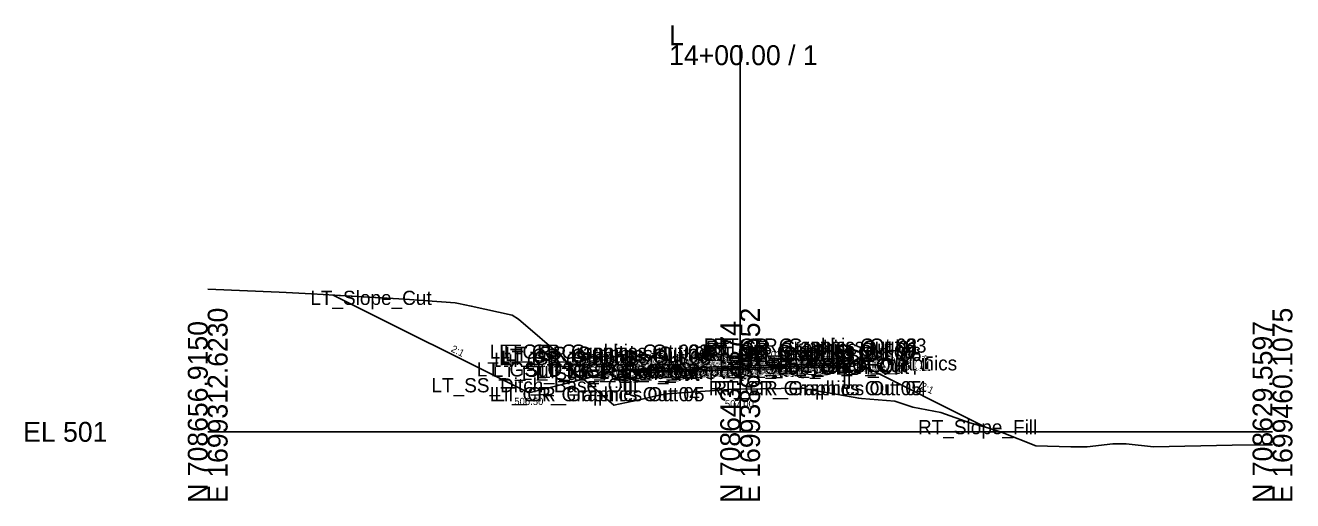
# Model space of a CAD drawing. Extents: x -63 to 1153, y -24 to 9522.
# Drawn here: x -25.7 to 152.8, y 4490.3 to 4557.3 of the extents above; entities that cross this region are included whole.
import ezdxf

# ---------------------------------------------------------------- set-up
doc = ezdxf.new("R2010")
doc.units = 0
for name, color, linetype in [('Default', 7, 'Continuous'), ('Exist Cross Section Cell', 7, 'Continuous'), ('Exist XS Center Line Elevation Label', 7, 'Continuous'), ('Exist XS Ground Line', 7, 'Continuous'), ('Prop CMT DNC', 7, 'Continuous'), ('Prop CMT Guardrail Graphics', 7, 'Continuous'), ('Prop CMT Pvmt Course 1', 7, 'Continuous'), ('Prop CMT Pvmt Course 2', 7, 'Continuous'), ('Prop CMT Pvmt Surface', 7, 'Continuous'), ('Prop CMT Pvmt Surface Overlay', 7, 'Continuous'), ('Prop CMT Pvmt Surface Shoulder', 7, 'Continuous'), ('Prop CMT Shld Paved Course 1', 7, 'Continuous'), ('Prop CMT Shld Paved Course 2', 7, 'Continuous'), ('Prop CMT Slope Grass', 7, 'Continuous'), ('Prop CMT Subgrade Earthwork', 7, 'Continuous'), ('Prop XS Ditch Standard Text', 7, 'Continuous'), ('Prop XS Earthwork Shape', 7, 'Continuous'), ('Prop XS EOT Tick Mark', 7, 'Continuous'), ('Prop XS SE Text', 7, 'Continuous'), ('Prop XS Side Slope Text', 7, 'Continuous')]:
    doc.layers.add(name, color=color, linetype=linetype)

msp = doc.modelspace()

# ---------------------------------------------------------------- linework, layer by layer
at = {"layer": 'Exist Cross Section Cell'}
for p, q in [((75, 4500), (75, 4554.45)), ((0, 4500), (75, 4500)), ((75, 4500), (150, 4500))]:
    msp.add_line(p, q, dxfattribs=at)
at = {"layer": 'Exist XS Ground Line'}
msp.add_lwpolyline([(0, 4520.1), (10.06, 4519.65), (11.06, 4519.64), (14.64, 4519.43), (27.78, 4518.71), (34.84, 4518.15), (35.32, 4518.07), (37.13, 4517.71), (42.9, 4516.45), (43.76, 4515.85), (50.12, 4510.4), (51.77, 4508.25), (53.39, 4507.04), (57.23, 4503.75), (59.9, 4504.3), (60.77, 4504.49), (63.41, 4505.1), (64.39, 4505.32), (64.77, 4505.34), (74.03, 4505.99), (75, 4506), (83.67, 4506.13), (83.87, 4506.13), (84.07, 4506.1), (84.46, 4506.02), (91.72, 4504.74), (92.1, 4504.7), (96.82, 4504.31), (99.31, 4503.46), (103.29, 4502.71), (107.37, 4501.25), (109.91, 4500.57), (111.94, 4499.91), (116.64, 4498.02), (121.6, 4497.91), (123.91, 4497.88), (127.52, 4498.3), (129.38, 4498.31), (133.24, 4497.89), (144.33, 4498.1), (149.42, 4498.18), (150, 4498.16)], dxfattribs=at)
at = {"layer": 'Prop CMT Guardrail Graphics'}
for points in [[(90.38, 4512.15), (89.05, 4512.15), (88.78, 4511.86)], [(88.78, 4511.86), (89.05, 4511.57)], [(89.05, 4511.57), (88.78, 4511.27)], [(90.38, 4506.15), (90.38, 4512.15)], [(58.84, 4505.3), (58.84, 4511.3)], [(58.84, 4511.3), (60.17, 4511.3), (60.44, 4511)], [(60.44, 4510.42), (60.17, 4510.13), (59.5, 4510.13)], [(59.5, 4510.13), (59.5, 4505.3)], [(60.44, 4511), (60.17, 4510.71)], [(60.17, 4510.71), (60.44, 4510.42)], [(88.78, 4511.27), (89.05, 4510.98), (89.72, 4510.98)], [(89.72, 4510.98), (89.72, 4506.15)], [(59.5, 4505.3), (58.84, 4505.3)], [(89.72, 4506.15), (90.38, 4506.15)]]:
    msp.add_lwpolyline(points, dxfattribs=at)
at = {"layer": 'Prop CMT Pvmt Course 1'}
for points in [[(75, 4509.24), (65, 4508.94)], [(65, 4508.69), (75, 4508.99)], [(65, 4508.94), (65, 4508.69)], [(75, 4509.24), (85, 4509.54)], [(85, 4509.29), (75, 4508.99)], [(75, 4509.11), (75, 4509.24)], [(75, 4509.11), (75, 4509.24)], [(75, 4508.99), (75, 4509.11), (75, 4509.11)], [(75, 4508.99), (75, 4509.11), (75, 4509.11)], [(85, 4509.54), (85, 4509.29)]]:
    msp.add_lwpolyline(points, dxfattribs=at)
at = {"layer": 'Prop CMT Pvmt Course 2'}
for points in [[(75, 4508.99), (65, 4508.69)], [(65, 4508.44), (75, 4508.74)], [(65, 4508.69), (65, 4508.44)], [(75, 4508.99), (85, 4509.29)], [(85, 4509.04), (75, 4508.74)], [(75, 4508.74), (75, 4508.99)], [(75, 4508.74), (75, 4508.99)], [(85, 4509.29), (85, 4509.04)]]:
    msp.add_lwpolyline(points, dxfattribs=at)
at = {"layer": 'Prop CMT Pvmt Surface'}
for points in [[(75, 4509.24), (65, 4508.94)], [(75, 4509.24), (85, 4509.54)]]:
    msp.add_lwpolyline(points, dxfattribs=at)
at = {"layer": 'Prop CMT Pvmt Surface Overlay'}
for points in [[(75, 4509.24), (65, 4508.94)], [(75, 4509.24), (85, 4509.54)]]:
    msp.add_lwpolyline(points, dxfattribs=at)
at = {"layer": 'Prop CMT Pvmt Surface Shoulder'}
for points in [[(65, 4508.94), (60.54, 4508.8)], [(85, 4509.54), (88.77, 4509.65)]]:
    msp.add_lwpolyline(points, dxfattribs=at)
at = {"layer": 'Prop CMT Shld Paved Course 1'}
for points in [[(65, 4508.94), (60.54, 4508.8), (60.28, 4508.55)], [(60.28, 4508.55), (65, 4508.69)], [(65, 4508.69), (65, 4508.94)], [(85, 4509.54), (88.77, 4509.65), (89.01, 4509.41)], [(85, 4509.29), (85, 4509.54)], [(89.01, 4509.41), (85, 4509.29)]]:
    msp.add_lwpolyline(points, dxfattribs=at)
at = {"layer": 'Prop CMT Shld Paved Course 2'}
for points in [[(60.28, 4508.55), (60.03, 4508.29)], [(60.03, 4508.29), (65, 4508.44)], [(65, 4508.69), (60.28, 4508.55)], [(60.28, 4508.55), (60.28, 4508.55)], [(65, 4508.44), (65, 4508.69)], [(85, 4509.29), (89.01, 4509.41)], [(85, 4509.04), (85, 4509.29)], [(89.26, 4509.16), (85, 4509.04)], [(89.01, 4509.41), (89.01, 4509.41)], [(89.01, 4509.41), (89.26, 4509.16)]]:
    msp.add_lwpolyline(points, dxfattribs=at)
at = {"layer": 'Prop CMT Slope Grass'}
for p, q in [((45.22, 4505.5), (17.69, 4519.26)), ((57.44, 4508.56), (45.22, 4505.5))]:
    msp.add_line(p, q, dxfattribs=at)
for points in [[(60.44, 4508.8), (57.44, 4508.56)], [(60.54, 4508.8), (60.44, 4508.8)], [(88.77, 4509.65), (88.78, 4509.65)], [(88.78, 4509.65), (91.78, 4509.56)], [(91.78, 4509.56), (109.59, 4500.66)]]:
    msp.add_lwpolyline(points, dxfattribs=at)
at = {"layer": 'Prop CMT Subgrade Earthwork'}
for points in [[(60.03, 4508.29), (59.59, 4508.73)], [(65, 4508.44), (60.03, 4508.29)], [(75, 4508.74), (65, 4508.44)], [(75, 4508.74), (85, 4509.04)], [(85, 4509.04), (89.26, 4509.16)], [(89.26, 4509.16), (89.71, 4509.62)]]:
    msp.add_lwpolyline(points, dxfattribs=at)
at = {"layer": 'Prop XS Earthwork Shape'}
for points in [[(34.84, 4518.15), (35.32, 4518.07), (37.13, 4517.71), (42.9, 4516.45), (43.76, 4515.85), (50.12, 4510.4), (51.77, 4508.25), (52.89, 4507.42), (45.22, 4505.5), (17.69, 4519.26), (27.78, 4518.71)], [(60.77, 4504.49), (63.41, 4505.1), (64.39, 4505.32), (64.77, 4505.34), (74.03, 4505.99), (75, 4506), (83.67, 4506.13), (83.87, 4506.13), (84.07, 4506.1), (84.46, 4506.02), (91.72, 4504.74), (92.1, 4504.7), (96.82, 4504.31), (99.31, 4503.46), (103.29, 4502.71), (107.37, 4501.25), (109.59, 4500.66), (91.78, 4509.56), (89.71, 4509.62), (89.26, 4509.16), (85, 4509.04), (75, 4508.74), (65, 4508.44), (60.03, 4508.29), (59.59, 4508.73), (57.44, 4508.56), (52.89, 4507.42), (53.39, 4507.04), (57.23, 4503.75), (59.9, 4504.3)]]:
    msp.add_lwpolyline(points, close=True, dxfattribs=at)
at = {"layer": 'Prop XS EOT Tick Mark'}
for points in [[(65, 4508.94), (65, 4509.94)], [(85, 4509.54), (85, 4510.54)]]:
    msp.add_lwpolyline(points, dxfattribs=at)

# ---------------------------------------------------------------- texts
at = {"layer": 'Default'}
msp.add_text('-', height=0.0001, dxfattribs=at).set_placement((0, 4500))
at = {"layer": 'Exist Cross Section Cell'}
for s, p in [('L', (65, 4554.45)), ('14+00.00 / 1', (65, 4551.65)), ('EL 501', (-26, 4498.6))]:
    msp.add_text(s, height=2.8, dxfattribs=at).set_placement(p)
for s, p in [('E 1699312.6230', (2.8, 4490)), ('E 1699386.3652', (77.8, 4490)), ('E 1699460.1075', (152.8, 4490)), ('N 708656.9150', (0, 4490)), ('N 708643.2374', (75, 4490)), ('N 708629.5597', (150, 4490))]:
    msp.add_text(s, height=2.8, rotation=90, dxfattribs=at).set_placement(p)
at = {"layer": 'Exist XS Center Line Elevation Label'}
msp.add_text('507.00', height=1, dxfattribs=at).set_placement((72.85, 4503.46))
at = {"layer": 'Prop CMT DNC'}
for s, p in [('LT_Slope_Cut', (14.45, 4517.87)), ('LT_GR_Graphics Out 03', (39.73, 4510.3)), ('LT_GR_Graphics Out 02', (41.07, 4510.3)), ('LT_GR_Graphics Out 09', (41.07, 4509.71)), ('LT_GR_Graphics Out 08', (41.34, 4509.42)), ('LT_GR_Graphics Out 01', (41.9, 4510)), ('RT_GR_Graphics Out 08', (69.63, 4510.27)), ('RT_GR_Graphics Out 02', (69.9, 4511.15)), ('RT_GR_Graphics Out 09', (69.9, 4510.57)), ('RT_GR_Graphics Out 07', (69.9, 4509.98)), ('RT_GR_Graphics Out 01', (70.2, 4510.86)), ('RT_GR_Graphics Out 06', (70.52, 4509.98)), ('RT_GR_Graphics Out 03', (71.23, 4511.15)), ('RT_TM_OEOT', (75.9, 4509.54)), ('LT_GS_OS_GR_Face_Graphics', (37.9, 4507.8)), ('LT_Sub_Trench_Out_DLT', (40.15, 4507.73)), ('LT_GR_Graphics Out 06', (40.35, 4509.13)), ('LT_GR_Graphics Out 07', (41.07, 4509.13)), ('LT_PS1_OEOP', (51.34, 4507.8)), ('LT_PV1_OEOT', (55.74, 4507.94)), ('LT_TM_OEOT', (55.94, 4508.94)), ('RT_PV1_OEEOP_W', (62.94, 4508.11)), ('LT_PV1_OEEOP_W', (62.98, 4508.11)), ('RT_Sub_OEEOP', (64.17, 4507.74)), ('LT_Sub_OEEOP', (64.21, 4507.74)), ('RT_PV2_OEEOP', (64.26, 4507.99)), ('LT_PV2_OEEOP', (64.31, 4507.99)), ('RT_GS_OS_GR_Face_Graphics', (66.19, 4508.65)), ('PV1_PGL_W', (67.58, 4508.11)), ('PV1_PGL', (69.47, 4508.24)), ('RT_Sub_Trench_Out_DLT', (70.23, 4508.62)), ('RT_Sub_Trench_Out', (73.41, 4508.16)), ('RT_PS2_Shelf_Out', (74.95, 4508.41)), ('RT_Sub_OEOT', (75.03, 4508.04)), ('RT_PV2_OEOT', (75.13, 4508.29)), ('RT_PV1_OEOT', (75.69, 4508.54)), ('RT_PS2_OEOP', (79.2, 4508.41)), ('RT_PS1_OEOP', (79.53, 4508.65)), ('RT_GS_OS_CTL', (81.1, 4508.56)), ('LT_Sub_Trench_Out', (44.23, 4507.29)), ('LT_PS2_Shelf_Out', (46.27, 4507.55)), ('LT_GS_OS_CTL', (46.81, 4507.56)), ('LT_PS2_OEOP', (50.52, 4507.55)), ('LT_Sub_OEOT', (55.08, 4507.44)), ('LT_PV2_OEOT', (55.17, 4507.69)), ('LT_SS_Ditch_Base_Out', (31.52, 4505.56)), ('LT_GR_Graphics Out 04', (39.73, 4504.3)), ('LT_GR_Graphics Out 05', (40.4, 4504.3)), ('RT_GR_Graphics Out 05', (70.57, 4505.15)), ('RT_GR_Graphics Out 04', (71.23, 4505.15)), ('RT_Slope_Fill', (100.06, 4499.66))]:
    msp.add_text(s, height=2, dxfattribs=at).set_placement(p)
at = {"layer": 'Prop XS Ditch Standard Text'}
msp.add_text('506.50', height=1, dxfattribs=at).set_placement((43.19, 4503.79))
at = {"layer": 'Prop XS SE Text'}
for p in [(68.22, 4510.03), (78.22, 4510.33)]:
    msp.add_text('0.030', height=1, rotation=1.7184, dxfattribs=at).set_placement(p)
at = {"layer": 'Prop XS Side Slope Text'}
for s, rotation, p in [('2:1', 333.4349, (34.18, 4511.36)), ('4:1', 14.0362, (52.49, 4508.09)), ('2:1', 333.4349, (100.31, 4506.13))]:
    msp.add_text(s, height=1, rotation=rotation, dxfattribs=at).set_placement(p)

doc.saveas('drawing.dxf')
